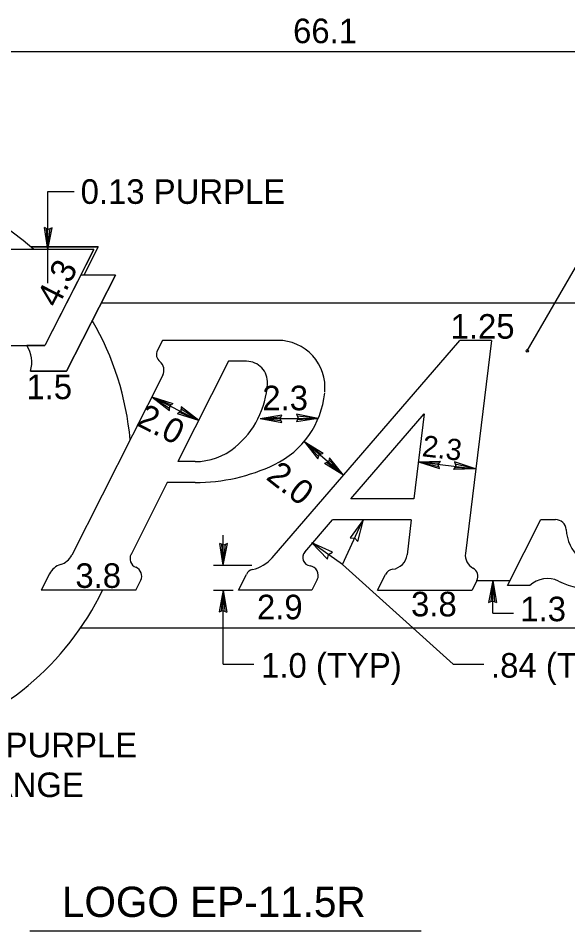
# Model space of a CAD drawing. Extents: x 10268197 to 10269179, y 2141503 to 2142677.
# Drawn here: x 10268876.28 to 10268891.94, y 2142087.47 to 2142113.47 of the extents above; entities that cross this region are included whole.
import ezdxf

# ---------------------------------------------------------------- set-up
doc = ezdxf.new("R2010")
doc.units = 0
for name, color, linetype in [('1', 7, 'Continuous'), ('20', 7, 'Continuous'), ('21', 7, 'Continuous'), ('3', 7, 'Continuous'), ('52', 7, 'Continuous'), ('Default', 7, 'Continuous')]:
    doc.layers.add(name, color=color, linetype=linetype)

msp = doc.modelspace()

# ---------------------------------------------------------------- linework, layer by layer
at = {"layer": '1'}
for p, q in [((10268878.438, 2142106.882), (10268869.814, 2142106.882)), ((10268878.562, 2142106.959), (10268876.644, 2142106.959)), ((10268878.438, 2142106.882), (10268877.045, 2142104.148)), ((10268878.562, 2142106.959), (10268878.151, 2142106.152)), ((10268878.066, 2142106.152), (10268877.045, 2142104.148)), ((10268877.657, 2142103.417), (10268879.05, 2142106.152)), ((10268879.05, 2142106.152), (10268877.657, 2142103.417)), ((10268879.05, 2142106.152), (10268878.066, 2142106.152)), ((10268879.05, 2142106.152), (10268878.066, 2142106.152)), ((10268878.648, 2142105.363), (10268908.253, 2142105.363)), ((10268880.391, 2142104.295), (10268880.248, 2142104.014)), ((10268883.676, 2142104.295), (10268880.391, 2142104.295)), ((10268883.517, 2142098.1), (10268888.861, 2142104.295)), ((10268889.76, 2142104.295), (10268888.861, 2142104.295)), ((10268889.76, 2142104.295), (10268889.02, 2142098.224)), ((10268876.005, 2142104.148), (10268877.045, 2142104.148)), ((10268877.045, 2142104.148), (10268876.526, 2142104.148)), ((10268882.277, 2142103.697), (10268880.833, 2142100.841)), ((10268882.787, 2142103.697), (10268882.277, 2142103.697)), ((10268877.657, 2142103.417), (10268876.634, 2142103.417)), ((10268876.634, 2142103.417), (10268877.657, 2142103.417)), ((10268880.4, 2142103.299), (10268877.808, 2142098.174)), ((10268885.754, 2142099.778), (10268887.847, 2142102.203)), ((10268887.847, 2142102.203), (10268887.552, 2142099.778)), ((10268881.321, 2142100.841), (10268880.833, 2142100.841)), ((10268880.53, 2142100.243), (10268879.497, 2142098.198)), ((10268881.32, 2142100.243), (10268880.53, 2142100.243)), ((10268887.552, 2142099.778), (10268885.754, 2142099.778)), ((10268884.446, 2142098.263), (10268885.237, 2142099.18)), ((10268887.479, 2142099.18), (10268885.237, 2142099.18)), ((10268887.479, 2142099.18), (10268887.358, 2142098.188)), ((10268890.219, 2142097.308), (10268891.169, 2142099.188)), ((10268891.169, 2142099.188), (10268891.59, 2142099.188)), ((10268877.171, 2142097.641), (10268876.937, 2142097.176)), ((10268879.629, 2142097.176), (10268879.771, 2142097.458)), ((10268882.554, 2142097.176), (10268882.781, 2142097.627)), ((10268884.802, 2142097.481), (10268884.647, 2142097.176)), ((10268886.518, 2142097.176), (10268886.747, 2142097.627)), ((10268889.347, 2142097.448), (10268889.21, 2142097.176)), ((10268879.629, 2142097.176), (10268876.937, 2142097.176)), ((10268884.647, 2142097.176), (10268882.554, 2142097.176)), ((10268886.518, 2142097.176), (10268889.21, 2142097.176)), ((10268890.854, 2142097.308), (10268890.219, 2142097.308)), ((10268878.065, 2142096.108), (10268903.538, 2142096.108))]:
    msp.add_line(p, q, dxfattribs=at)
for centre, radius, start, end in [((10268871.316, 2142100.743), 8.187, 48.5904, 218.8792), ((10268871.316, 2142100.743), 8.187, 5.051, 30.1953), ((10268883.675, 2142102.949), 1.346, 354.6609, 90), ((10268875.793, 2142103.666), 0.877, 343.4611, 33.2756), ((10268875.793, 2142103.666), 0.877, 343.4611, 33.2756), ((10268882.787, 2142103.099), 0.598, 356.6133, 90), ((10268880.846, 2142103.214), 2.542, 309.3947, 356.6133), ((10268882.483, 2142103.049), 2.542, 295.579, 354.2619), ((10268881.321, 2142102.636), 1.795, 270, 309.3947), ((10268881.321, 2142105.478), 5.235, 270, 295.579), ((10268891.59, 2142098.889), 0.299, 3.1643, 90), ((10268893.083, 2142098.971), 1.196, 183.1643, 270), ((10268884.627, 2142098.107), 0.239, 139.1995, 262.5416), ((10268889.436, 2142098.174), 0.419, 173.0593, 241.464), ((10268879.736, 2142098.077), 0.269, 153.1708, 247.5682), ((10268886.883, 2142098.246), 0.479, 277.9506, 353.082), ((10268879.531, 2142097.579), 0.269, 333.1431, 67.5682), ((10268884.561, 2142097.603), 0.269, 333.166, 82.5416), ((10268886.987, 2142097.506), 0.269, 97.9506, 153.1923), ((10268889.107, 2142097.569), 0.269, 333.284, 61.464), ((10268871.316, 2142100.743), 8.187, 237.0648, 334.1734)]:
    msp.add_arc(centre, radius, start, end, dxfattribs=at)
for centre, major_axis, start_param, end_param in [((10268880.481, 2142103.894), (0, -0.264), 4.240773, 5.605302), ((10268880.12, 2142103.442), (0, -0.316), 1.099604, 2.46371), ((10268877.342, 2142098.414), (0, -0.527), 0.286787, 1.099486), ((10268882.727, 2142098.794), (0, -1.055), 0.22194, 0.855152), ((10268877.638, 2142097.402), (0, -0.527), 3.428379, 4.240701), ((10268883.015, 2142097.508), (0, -0.264), 3.363532, 4.241567), ((10268891.356, 2142096.77), (0, -0.738), 2.69443, 3.895387), ((10268892.805, 2142099.813), (0, -2.637), 5.836023, 6.283185)]:
    msp.add_ellipse(centre, major_axis=major_axis, ratio=0.992614, start_param=start_param, end_param=end_param, dxfattribs=at)
at = {"layer": '20'}
for p, q in [((10268908.253, 2142112.514), (10268861.216, 2142112.514)), ((10268890.784, 2142103.994), (10268894.555, 2142110.527)), ((10268877.128, 2142106.958), (10268877.128, 2142108.54)), ((10268877.128, 2142108.54), (10268877.878, 2142108.54)), ((10268877.128, 2142105.922), (10268877.128, 2142106.882)), ((10268880.09, 2142102.686), (10268881.424, 2142102.011)), ((10268883.171, 2142102.071), (10268884.83, 2142102.071)), ((10268885.545, 2142100.452), (10268884.43, 2142101.414)), ((10268887.68, 2142100.834), (10268889.313, 2142100.636)), ((10268885.517, 2142097.911), (10268886.113, 2142099.188)), ((10268882.125, 2142097.888), (10268882.125, 2142098.746)), ((10268885.517, 2142097.911), (10268884.648, 2142098.528)), ((10268881.843, 2142097.888), (10268882.941, 2142097.888)), ((10268888.674, 2142095.065), (10268885.517, 2142097.911)), ((10268889.347, 2142097.448), (10268890.29, 2142097.448)), ((10268889.803, 2142096.519), (10268889.804, 2142097.448)), ((10268881.843, 2142097.176), (10268882.406, 2142097.176)), ((10268882.125, 2142095.065), (10268882.125, 2142097.176)), ((10268889.803, 2142096.519), (10268890.386, 2142096.519)), ((10268882.125, 2142095.065), (10268882.997, 2142095.065)), ((10268888.674, 2142095.065), (10268889.546, 2142095.065))]:
    msp.add_line(p, q, dxfattribs=at)
msp.add_circle((10268890.784, 2142103.994), 0.0356, dxfattribs=at)
at = {"layer": '21'}
for p, q in [((10268877.128, 2142106.882), (10268877.029, 2142107.506)), ((10268877.138, 2142107.456), (10268877.029, 2142107.506)), ((10268877.128, 2142106.882), (10268877.086, 2142107.48)), ((10268877.128, 2142106.882), (10268877.249, 2142107.502)), ((10268877.128, 2142106.882), (10268877.191, 2142107.478)), ((10268877.249, 2142107.502), (10268877.138, 2142107.456)), ((10268880.09, 2142102.686), (10268880.691, 2142102.493)), ((10268880.09, 2142102.686), (10268880.589, 2142102.299)), ((10268880.09, 2142102.686), (10268880.594, 2142102.362)), ((10268880.09, 2142102.686), (10268880.642, 2142102.454)), ((10268880.589, 2142102.299), (10268880.598, 2142102.418)), ((10268880.598, 2142102.418), (10268880.691, 2142102.493)), ((10268880.925, 2142102.398), (10268880.916, 2142102.279)), ((10268881.424, 2142102.011), (10268880.925, 2142102.398)), ((10268880.916, 2142102.279), (10268880.823, 2142102.204)), ((10268881.424, 2142102.011), (10268880.823, 2142102.204)), ((10268881.424, 2142102.011), (10268880.873, 2142102.243)), ((10268881.424, 2142102.011), (10268880.92, 2142102.336)), ((10268883.171, 2142102.071), (10268883.794, 2142102.17)), ((10268883.171, 2142102.071), (10268883.768, 2142102.113)), ((10268883.745, 2142102.061), (10268883.794, 2142102.17)), ((10268884.83, 2142102.071), (10268884.21, 2142102.191)), ((10268884.21, 2142102.191), (10268884.255, 2142102.081)), ((10268884.83, 2142102.071), (10268884.234, 2142102.134)), ((10268883.171, 2142102.071), (10268883.791, 2142101.951)), ((10268883.171, 2142102.071), (10268883.767, 2142102.009)), ((10268883.791, 2142101.951), (10268883.745, 2142102.061)), ((10268884.255, 2142102.081), (10268884.206, 2142101.972)), ((10268884.83, 2142102.071), (10268884.206, 2142101.972)), ((10268884.83, 2142102.071), (10268884.232, 2142102.029)), ((10268884.43, 2142101.414), (10268884.967, 2142101.082)), ((10268884.43, 2142101.414), (10268884.821, 2142100.918)), ((10268884.43, 2142101.414), (10268884.841, 2142100.978)), ((10268884.43, 2142101.414), (10268884.91, 2142101.056)), ((10268884.859, 2142101.032), (10268884.967, 2142101.082)), ((10268884.821, 2142100.918), (10268884.859, 2142101.032)), ((10268885.117, 2142100.835), (10268885.008, 2142100.784)), ((10268885.545, 2142100.452), (10268885.066, 2142100.811)), ((10268885.154, 2142100.948), (10268885.117, 2142100.835)), ((10268885.545, 2142100.452), (10268885.134, 2142100.888)), ((10268885.545, 2142100.452), (10268885.154, 2142100.948)), ((10268887.68, 2142100.834), (10268888.311, 2142100.857)), ((10268887.68, 2142100.834), (10268888.281, 2142100.64)), ((10268887.68, 2142100.834), (10268888.264, 2142100.7)), ((10268887.68, 2142100.834), (10268888.278, 2142100.804)), ((10268888.249, 2142100.755), (10268888.311, 2142100.857)), ((10268889.313, 2142100.636), (10268888.712, 2142100.83)), ((10268888.712, 2142100.83), (10268888.744, 2142100.715)), ((10268885.545, 2142100.452), (10268885.008, 2142100.784)), ((10268888.281, 2142100.64), (10268888.249, 2142100.755)), ((10268888.744, 2142100.715), (10268888.682, 2142100.613)), ((10268889.313, 2142100.636), (10268888.682, 2142100.613)), ((10268889.313, 2142100.636), (10268888.715, 2142100.666)), ((10268889.313, 2142100.636), (10268888.729, 2142100.77)), ((10268882.125, 2142097.888), (10268882.026, 2142098.511)), ((10268882.135, 2142098.462), (10268882.026, 2142098.511)), ((10268882.125, 2142097.888), (10268882.083, 2142098.485)), ((10268882.125, 2142097.888), (10268882.245, 2142098.508)), ((10268882.125, 2142097.888), (10268882.187, 2142098.484)), ((10268882.245, 2142098.508), (10268882.135, 2142098.462)), ((10268889.804, 2142097.448), (10268889.683, 2142096.828)), ((10268889.804, 2142097.448), (10268889.741, 2142096.852)), ((10268889.804, 2142097.448), (10268889.902, 2142096.824)), ((10268889.804, 2142097.448), (10268889.845, 2142096.85)), ((10268882.125, 2142097.176), (10268882.005, 2142096.556)), ((10268882.125, 2142097.176), (10268882.062, 2142096.58)), ((10268882.125, 2142097.176), (10268882.224, 2142096.552)), ((10268882.125, 2142097.176), (10268882.167, 2142096.579)), ((10268889.683, 2142096.828), (10268889.794, 2142096.874)), ((10268889.794, 2142096.874), (10268889.902, 2142096.824)), ((10268882.005, 2142096.556), (10268882.115, 2142096.602)), ((10268882.115, 2142096.602), (10268882.224, 2142096.552))]:
    msp.add_line(p, q, dxfattribs=at)
at = {"layer": '3'}
msp.add_lwpolyline([(10268876.644, 2142106.959), (10268878.562, 2142106.959), (10268878.151, 2142106.152), (10268878.066, 2142106.152), (10268878.438, 2142106.882), (10268876.731, 2142106.883)], close=True, dxfattribs=at)
at = {"layer": '52'}
for p, q in [((10268886.114, 2142099.188), (10268885.736, 2142098.668)), ((10268885.953, 2142098.566), (10268886.114, 2142099.188)), ((10268884.648, 2142098.528), (10268885.093, 2142098.063)), ((10268885.231, 2142098.259), (10268884.648, 2142098.528)), ((10268885.736, 2142098.668), (10268885.867, 2142098.66)), ((10268885.867, 2142098.66), (10268885.953, 2142098.566)), ((10268885.124, 2142098.191), (10268885.231, 2142098.259)), ((10268885.093, 2142098.063), (10268885.124, 2142098.191))]:
    msp.add_line(p, q, dxfattribs=at)
at = {"layer": 'Default'}
msp.add_line((10268876.612, 2142087.473), (10268887.76, 2142087.473), dxfattribs=at)

# ---------------------------------------------------------------- texts
at = {"layer": '1'}
msp.add_text('LOGO EP-11.5R', height=0.8624, dxfattribs=at).set_placement((10268877.528, 2142087.866))
at = {"layer": '20'}
for s, p in [('66.1', (10268884.112, 2142112.762)), ('0.13 PURPLE', (10268878.061, 2142108.184)), ('1.25', (10268888.599, 2142104.342)), ('1.5', (10268876.515, 2142102.619)), ('2.3', (10268883.236, 2142102.303)), ('3.8', (10268877.911, 2142097.242)), ('2.9', (10268883.083, 2142096.347)), ('3.8', (10268887.473, 2142096.43)), ('1.3', (10268890.585, 2142096.292)), ('1.0 (TYP)', (10268883.201, 2142094.684)), ('.84 (TYP)', (10268889.75, 2142094.684)), ('PURPLE', (10268875.925, 2142092.415)), ('ORANGE', (10268874.096, 2142091.282))]:
    msp.add_text(s, height=0.7, dxfattribs=at).set_placement(p)
for s, height, rotation, p in [('4.3', 0.7, 63.001, (10268877.402, 2142105.194)), ('2.0', 0.7, 333.1665, (10268879.614, 2142101.89)), ('2.3', 0.6037, 353.0765, (10268887.766, 2142100.996)), ('2.0', 0.7, 321.8741, (10268883.313, 2142100.355))]:
    msp.add_text(s, height=height, rotation=rotation, dxfattribs=at).set_placement(p)

doc.saveas('drawing.dxf')
